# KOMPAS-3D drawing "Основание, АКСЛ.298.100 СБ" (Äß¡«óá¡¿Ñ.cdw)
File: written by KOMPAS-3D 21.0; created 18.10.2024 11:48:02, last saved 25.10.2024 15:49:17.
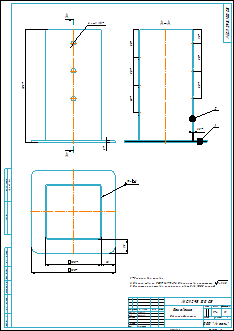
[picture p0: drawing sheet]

Sheet 1: A2, portrait

Document properties: Полное имя файла: Основание.a3d; Автор: Алексей Бочаров; Масса: 1.739154

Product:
- Part/product: Основание  | designation АКСЛ.298.100 СБ
    Масса: 1.739154
    Форматы листов документа: A2
    source file: Основание спецификация.spw
  - Component [detail]: Пластина основания  | designation АКСЛ.298.101  | pos. 1  | Масса: 0.528257; Форматы листов документа: A4; source file: Пластина основания.cdw, Пластина основания.m3d
  - Component [detail]: Профиль L = 200 мм  | designation АКСЛ.298.401  | pos. 2  | Масса: 1.210897; source file: ..\КВАТРО\АКСЛ.298.401 - Профиль L = 200 мм.cdw, ..\КВАТРО\Профиль L = 200 мм.m3d

Title block, sheet 1: Наименование: Основание / Сборочный чертеж; designation: АКСЛ.298.100 СБ; Масса: 1,74; Количество листов документа: 1; organisation: ООО "Аксель"; Форматы листов документа: A2; stored path: C:\Users\Алексей Бочаров\YandexDisk\Соединения бруса\Соединения бруса\ОСНОВАНИЕ\Основание.cdw; Разработал: Бочаров; Проверил: Захаров; Утвердил: Гелетей

Views: Вид 1, Спереди, Проекционный вид 2, Местный разрез 1, Проекционный вид 3
Referenced files in C:\Users\Алексей Бочаров\YandexDisk\Соединения бруса\Соединения бруса\ОСНОВАНИЕ\: Основание.a3d, Пластина основания.m3d
Referenced files in C:\Users\Алексей Бочаров\YandexDisk\Соединения бруса\Соединения бруса\КВАТРО\: Профиль L = 200 мм.m3d
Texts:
  АКСЛ.298.100
  Пластина основания
  АКСЛ.298.101
  АКСЛ.298.101 Пластина основания
  Профиль L = 200 мм
  АКСЛ.298.401
  АКСЛ.298.401 Профиль L = 200 мм
  АКСЛ.298.100 СБ Основание
Dimensions and other numbers on the sheet: 203; 6 отв.; 8; 3; 50; 25; 2,5; 2; 1; 150; 100; 1:1; 1,74

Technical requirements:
  *Размеры для справок.
  Сварные швы по ГОСТ 14771-76. Сварные швы зачистить  Ra 12,5.
  Покрытие порошковое полимерное, цвет RAL 9005 черный.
